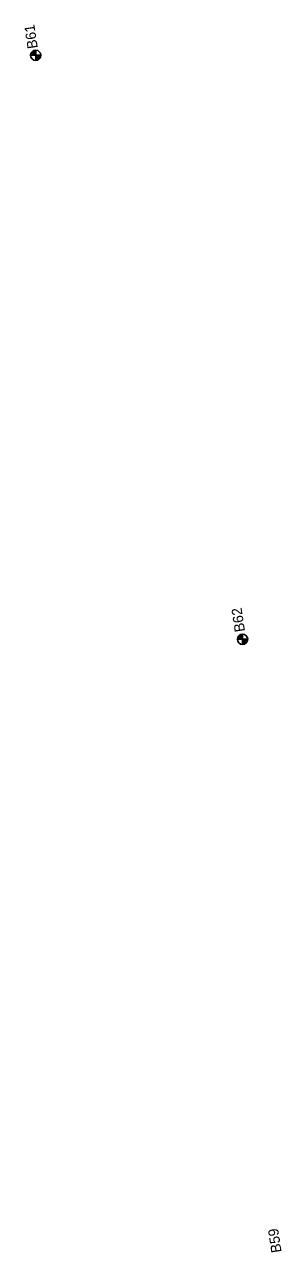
# Model space of a CAD drawing. Extents: x 345549 to 379569, y 127949 to 230467.
# Drawn here: x 359449 to 359699, y 162889 to 164088 of the extents above; entities that cross this region are included whole.
import ezdxf

# ---------------------------------------------------------------- set-up
doc = ezdxf.new("R2010")
doc.units = 0
doc.layers.add('E_SOIL_BORE2 [KAPUR_CADDS_LEVELS]', color=7, linetype='Continuous')
doc.layers.add('P_MARK', color=7, linetype='Continuous')

msp = doc.modelspace()

# ---------------------------------------------------------------- linework, layer by layer
at = {"layer": 'P_MARK'}
for p, q in [((359459.6, 164063.3), (359459.6, 164053.3)), ((359454.6, 164058.3), (359464.6, 164058.3)), ((359656.6, 163487.9), (359666.6, 163487.9)), ((359661.6, 163492.9), (359661.6, 163482.9))]:
    msp.add_line(p, q, dxfattribs=at)
for centre in [(359459.6, 164058.3), (359661.6, 163487.9)]:
    msp.add_circle(centre, 5, dxfattribs=at)
for centre, radius, start, end in [((359459.6, 164058.3), 4.5, 89.9869, 179.9869), ((359459.6, 164058.3), 4, 89.9869, 179.9869), ((359459.6, 164058.3), 3.5, 89.9869, 179.9869), ((359459.6, 164058.3), 3, 89.9869, 179.9869), ((359459.6, 164058.3), 2.5, 89.9869, 179.9869), ((359459.6, 164058.3), 2, 89.9869, 179.9869), ((359459.6, 164058.3), 1.5, 89.9869, 179.9869), ((359459.6, 164058.3), 1, 89.9869, 179.9869), ((359459.6, 164058.3), 0.5, 89.9869, 179.9869), ((359459.6, 164058.3), 4.5, 269.9869, 359.9869), ((359459.6, 164058.3), 4, 269.9869, 359.9869), ((359459.6, 164058.3), 3.5, 269.9869, 359.9869), ((359459.6, 164058.3), 3, 269.9869, 359.9869), ((359459.6, 164058.3), 2.5, 269.9869, 359.9869), ((359459.6, 164058.3), 2, 269.9869, 359.9869), ((359459.6, 164058.3), 1.5, 269.9869, 359.9869), ((359459.6, 164058.3), 1, 269.9869, 359.9869), ((359459.6, 164058.3), 0.5, 269.9869, 359.9869), ((359661.6, 163487.9), 4.5, 89.9869, 179.9869), ((359661.6, 163487.9), 4, 89.9869, 179.9869), ((359661.6, 163487.9), 3.5, 89.9869, 179.9869), ((359661.6, 163487.9), 3, 89.9869, 179.9869), ((359661.6, 163487.9), 2.5, 89.9869, 179.9869), ((359661.6, 163487.9), 2, 89.9869, 179.9869), ((359661.6, 163487.9), 1.5, 89.9869, 179.9869), ((359661.6, 163487.9), 1, 89.9869, 179.9869), ((359661.6, 163487.9), 0.5, 89.9869, 179.9869), ((359661.6, 163487.9), 4.5, 269.9869, 359.9869), ((359661.6, 163487.9), 4, 269.9869, 359.9869), ((359661.6, 163487.9), 3.5, 269.9869, 359.9869), ((359661.6, 163487.9), 3, 269.9869, 359.9869), ((359661.6, 163487.9), 2.5, 269.9869, 359.9869), ((359661.6, 163487.9), 2, 269.9869, 359.9869), ((359661.6, 163487.9), 1.5, 269.9869, 359.9869), ((359661.6, 163487.9), 1, 269.9869, 359.9869), ((359661.6, 163487.9), 0.5, 269.9869, 359.9869)]:
    msp.add_arc(centre, radius, start, end, dxfattribs=at)

# ---------------------------------------------------------------- texts
at = {"layer": 'E_SOIL_BORE2 [KAPUR_CADDS_LEVELS]'}
for s, p in [('B61', (359461.7, 164065.5)), ('B62', (359664, 163495.8)), ('B59', (359699.7, 162889.5))]:
    msp.add_text(s, height=10, rotation=98.5151, dxfattribs=at).set_placement(p)

doc.saveas('drawing.dxf')
